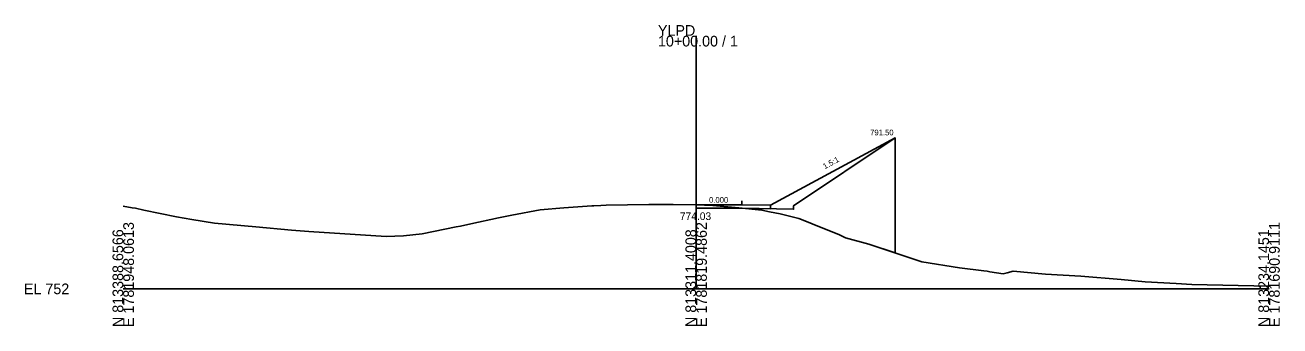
# Model space of a CAD drawing. Extents: x -26 to 353, y -10 to 9080.
# Drawn here: x -25.7 to 302.8, y -9.7 to 69 of the extents above; entities that cross this region are included whole.
import ezdxf

# ---------------------------------------------------------------- set-up
doc = ezdxf.new("R2010")
doc.units = 0
for name, color, linetype in [('Default', 7, 'Continuous'), ('Exist Cross Section Cell', 7, 'Continuous'), ('Exist XS Center Line Elevation Label', 7, 'Continuous'), ('Exist XS Ground Line', 7, 'Continuous'), ('Prop XS Ditch Standard Text', 7, 'Continuous'), ('Prop XS Dump Level', 7, 'Continuous'), ('Prop XS Earthwork Shape', 7, 'Continuous'), ('Prop XS EOT Tick Mark', 7, 'Continuous'), ('Prop XS Finish Grade Earthwork', 7, 'Continuous'), ('Prop XS Finish Grade Paved Shoulder', 7, 'Continuous'), ('Prop XS Finish Grade Pavement', 7, 'Continuous'), ('Prop XS SE Text', 7, 'Continuous'), ('Prop XS Side Slope Text', 7, 'Continuous'), ('Prop XS Subgrade Earthwork', 7, 'Continuous')]:
    doc.layers.add(name, color=color, linetype=linetype)

msp = doc.modelspace()

# ---------------------------------------------------------------- linework, layer by layer
at = {"layer": 'Default'}
msp.add_line((150, 0), (150, 0), dxfattribs=at)
at = {"layer": 'Exist Cross Section Cell'}
for p, q in [((150, 0), (150, 66.24)), ((0, 0), (150, 0)), ((150, 0), (300, 0))]:
    msp.add_line(p, q, dxfattribs=at)
at = {"layer": 'Exist XS Ground Line'}
for p, q in [((0, 21.66), (2.33, 21.24)), ((2.33, 21.24), (3.19, 21.11)), ((3.19, 21.11), (5.42, 20.64)), ((5.42, 20.64), (13.94, 18.85)), ((101.71, 19.28), (109.16, 20.71)), ((109.16, 20.71), (115.33, 21.21)), ((115.33, 21.21), (122.71, 21.7)), ((122.71, 21.7), (123.24, 21.74)), ((123.24, 21.74), (125.01, 21.86)), ((125.01, 21.86), (126.43, 21.95)), ((126.43, 21.95), (137.6, 22.07)), ((137.6, 22.07), (138.09, 22.08)), ((138.09, 22.08), (143.97, 22.06)), ((143.97, 22.06), (150, 22.03)), ((150, 22.03), (150, 22.03)), ((150, 22.03), (150, 22.03)), ((150, 22.03), (154.38, 21.86)), ((154.38, 21.86), (161.21, 21.19)), ((161.21, 21.19), (167.2, 20.61)), ((167.2, 20.61), (169.24, 20.2)), ((169.24, 20.2), (171.98, 19.66)), ((13.94, 18.85), (17.94, 18.19)), ((17.94, 18.19), (23.92, 17.17)), ((23.92, 17.17), (34.7, 16.23)), ((87.13, 16.2), (88.31, 16.43)), ((88.31, 16.43), (90.99, 17.01)), ((90.99, 17.01), (98.29, 18.6)), ((98.29, 18.6), (101.71, 19.28)), ((171.98, 19.66), (176.22, 18.56)), ((176.22, 18.56), (176.89, 18.38)), ((176.89, 18.38), (177.56, 18.15)), ((177.56, 18.15), (180.36, 17.02)), ((180.36, 17.02), (187.56, 14.18)), ((34.7, 16.23), (44.09, 15.4)), ((44.09, 15.4), (48.62, 15.02)), ((48.62, 15.02), (68.83, 13.73)), ((68.83, 13.73), (73.41, 13.92)), ((73.41, 13.92), (78.24, 14.4)), ((78.24, 14.4), (87.13, 16.2)), ((187.56, 14.18), (189.11, 13.4)), ((189.11, 13.4), (195.18, 11.74)), ((195.18, 11.74), (209.06, 7.05)), ((209.06, 7.05), (218.95, 5.47)), ((218.95, 5.47), (225.3, 4.71)), ((225.3, 4.71), (226.23, 4.59)), ((226.23, 4.59), (226.87, 4.48)), ((226.87, 4.48), (230.36, 3.93)), ((230.36, 3.93), (231.42, 4.2)), ((231.42, 4.2), (233.04, 4.61)), ((233.04, 4.61), (241.46, 3.85)), ((241.46, 3.85), (250.69, 3.32)), ((250.69, 3.32), (261.24, 2.47)), ((261.24, 2.47), (267.6, 1.83)), ((267.6, 1.83), (275.64, 1.42)), ((275.64, 1.42), (279.74, 1.13)), ((279.74, 1.13), (300, 0.72))]:
    msp.add_line(p, q, dxfattribs=at)
at = {"layer": 'Prop XS Dump Level'}
msp.add_line((162, 22.03), (150, 22.03), dxfattribs=at)
at = {"layer": 'Prop XS Earthwork Shape'}
for points in [[(162.04, 21.11), (167.2, 20.61), (169.24, 20.2), (171.98, 19.66), (176.22, 18.56), (176.89, 18.38), (177.56, 18.15), (180.36, 17.02), (187.56, 14.18), (189.11, 13.4), (195.18, 11.74), (202.11, 9.4), (202.11, 39.5), (175.5, 21.76), (175.5, 20.84)], [(161.21, 21.19), (162.04, 21.11), (161.99, 21.11), (150, 21.11), (150, 22.03), (154.38, 21.86)]]:
    msp.add_lwpolyline(points, close=True, dxfattribs=at)
at = {"layer": 'Prop XS EOT Tick Mark'}
for p, q in [((150, 22.03), (150, 23.03)), ((162, 22.03), (162, 23.03))]:
    msp.add_line(p, q, dxfattribs=at)
at = {"layer": 'Prop XS Finish Grade Earthwork'}
for p, q in [((169.5, 21.88), (202.11, 39.5)), ((202.11, 39.5), (202.11, 9.4))]:
    msp.add_line(p, q, dxfattribs=at)
at = {"layer": 'Prop XS Finish Grade Paved Shoulder'}
msp.add_line((162, 22.03), (169.5, 21.88), dxfattribs=at)
at = {"layer": 'Prop XS Finish Grade Pavement'}
msp.add_line((150, 22.03), (162, 22.03), dxfattribs=at)
at = {"layer": 'Prop XS Subgrade Earthwork'}
for p, q in [((150, 21.11), (150, 22.03)), ((161.99, 21.11), (150, 21.11)), ((161.99, 21.11), (169.5, 20.96)), ((169.5, 20.96), (169.5, 21.88))]:
    msp.add_line(p, q, dxfattribs=at)

# ---------------------------------------------------------------- texts
at = {"layer": 'Exist Cross Section Cell'}
for s, p in [('YLPD', (140, 66.24)), ('10+00.00 / 1', (140, 63.44)), ('EL 752', (-26, -1.4))]:
    msp.add_text(s, height=2.8, dxfattribs=at).set_placement(p)
for s, p in [('E 1781948.0613', (2.8, -10)), ('E 1781819.4862', (152.8, -10)), ('E 1781690.9111', (302.8, -10)), ('N 813388.6566', (0, -10)), ('N 813311.4008', (150, -10)), ('N 813234.1451', (300, -10))]:
    msp.add_text(s, height=2.8, rotation=90, dxfattribs=at).set_placement(p)
at = {"layer": 'Exist XS Center Line Elevation Label'}
msp.add_text('774.03', height=2, dxfattribs=at).set_placement((145.75, 18.03))
at = {"layer": 'Prop XS Ditch Standard Text'}
msp.add_text('791.50', height=1.5, dxfattribs=at).set_placement((195.55, 40.18))
at = {"layer": 'Prop XS SE Text'}
msp.add_text('0.000', height=1.5, dxfattribs=at).set_placement((153.38, 22.53))
at = {"layer": 'Prop XS Side Slope Text'}
msp.add_text('1.5:1', height=1.5, rotation=28.3835, dxfattribs=at).set_placement((183.69, 31.28))

doc.saveas('drawing.dxf')
